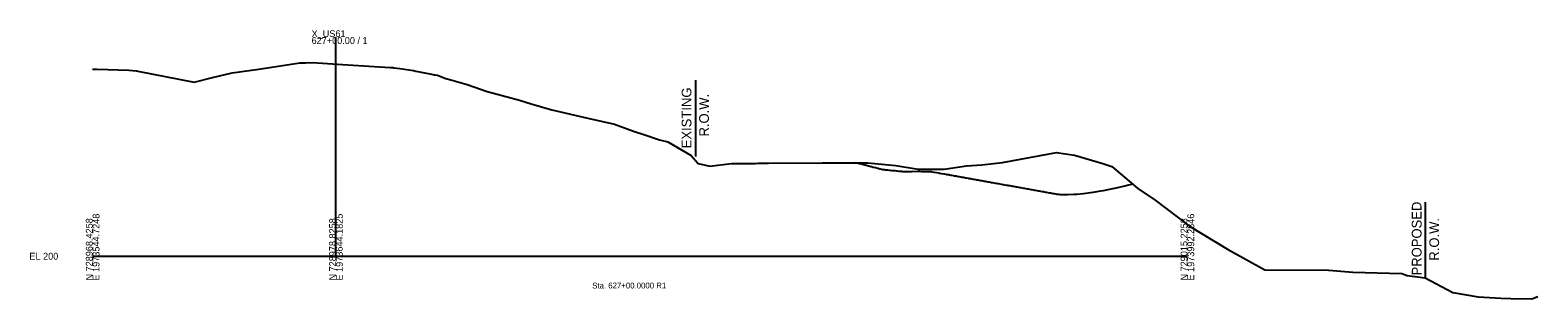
# Model space of a CAD drawing. Extents: x -26 to 630, y -39 to 9098.
# Drawn here: x -26 to 594, y 7482 to 7593 of the extents above; entities that cross this region are included whole.
import ezdxf

# ---------------------------------------------------------------- set-up
doc = ezdxf.new("R2010")
doc.units = 0
for name, color, linetype in [('Default', 7, 'Continuous'), ('Draft_XS_Grid', 7, 'Continuous'), ('Draft_XS_Text', 7, 'Continuous'), ('DTM_X_GROUND', 7, 'Continuous'), ('X_DTM_CONTOURS_MAJOR', 7, 'Continuous'), ('XS_CELL', 7, 'Continuous'), ('XS_P_GROUND', 7, 'Continuous'), ('XS_P_ROW', 7, 'Continuous'), ('XS_X_ROW', 7, 'Continuous')]:
    doc.layers.add(name, color=color, linetype=linetype)

msp = doc.modelspace()

# ---------------------------------------------------------------- linework, layer by layer
at = {"layer": 'DTM_X_GROUND'}
msp.add_lwpolyline([(0, 7576.89), (0.6, 7576.89), (1.9, 7576.85), (14.88, 7576.44), (17.86, 7576.17), (17.96, 7576.16), (18.58, 7576.04), (41.66, 7571.5), (49.31, 7573.36), (57.4, 7575.29), (68.36, 7576.79), (85.15, 7579.38), (87.49, 7579.49), (88.86, 7579.55), (92.36, 7579.36), (102.67, 7578.79), (122.32, 7577.54), (123.58, 7577.45), (123.78, 7577.43), (126.22, 7577.09), (131.88, 7576.23), (132.85, 7576.05), (134.36, 7575.75), (139.24, 7574.76), (140.31, 7574.45), (140.8, 7574.55), (141.71, 7574.4), (144.8, 7573.16), (145.16, 7573.05), (147.21, 7572.46), (154, 7570.58), (162.19, 7567.69), (164.8, 7567), (175.47, 7564.13), (180.27, 7562.58), (188.73, 7560.15), (203.61, 7556.66), (214.46, 7554.19), (222.32, 7551.38), (226.56, 7550.03), (233.04, 7547.84), (236.48, 7546.95), (245.98, 7541.43), (248.95, 7538.09), (253.64, 7537.01), (262.64, 7538.07), (270.68, 7538.05), (272.47, 7538.05), (273.52, 7538.22), (275.9, 7538.18), (277.87, 7538.15), (299.83, 7538.33), (299.94, 7538.33), (299.94, 7538.33), (300.02, 7538.35), (300.35, 7538.4), (318.65, 7538.33), (330.09, 7537.29), (339.33, 7535.72), (350.03, 7535.8), (359.25, 7537.13), (365.54, 7537.58), (373.93, 7538.55), (396.2, 7542.55), (403.53, 7541.51), (415.27, 7538.07), (418.87, 7536.9), (429.65, 7527.82), (436.78, 7523.06), (450.91, 7512.29), (466.52, 7502.84), (481.87, 7494.36), (507.99, 7494.2), (508.1, 7494.2), (508.17, 7494.2), (518.04, 7493.48), (538.13, 7492.96), (540.32, 7492.03), (547.73, 7491.14), (559.09, 7485.1), (569.52, 7483.3), (578.84, 7482.73), (582.95, 7482.65), (591.51, 7482.5), (594.05, 7483.51)], dxfattribs=at)
at = {"layer": 'XS_CELL'}
for p, q in [((100, 7500), (100, 7590)), ((0, 7500), (100, 7500)), ((100, 7500), (450, 7500))]:
    msp.add_line(p, q, dxfattribs=at)
at = {"layer": 'XS_P_GROUND'}
msp.add_lwpolyline([(427.5, 7529.63), (425.19, 7529.04), (424.86, 7528.97), (419.98, 7527.85), (419.15, 7527.68), (415.33, 7526.92), (414.32, 7526.75), (411.07, 7526.2), (408.24, 7525.82), (407.11, 7525.67), (404.54, 7525.4), (403.36, 7525.28), (400.88, 7525.18), (399.35, 7525.15), (398.89, 7525.19), (398.34, 7525.23), (397.88, 7525.27), (397.33, 7525.31), (396.88, 7525.35), (396.36, 7525.4), (396.34, 7525.4), (396.32, 7525.4), (395.86, 7525.49), (395.31, 7525.58), (394.85, 7525.67), (394.3, 7525.76), (393.83, 7525.85), (393.29, 7525.95), (392.82, 7526.03), (392.28, 7526.13), (391.81, 7526.21), (391.27, 7526.31), (390.8, 7526.39), (390.26, 7526.49), (389.79, 7526.57), (389.25, 7526.67), (388.78, 7526.75), (388.24, 7526.85), (387.76, 7526.93), (387.23, 7527.03), (386.75, 7527.12), (386.22, 7527.21), (385.74, 7527.3), (385.21, 7527.39), (384.72, 7527.48), (384.2, 7527.57), (383.71, 7527.66), (383.19, 7527.75), (382.7, 7527.84), (382.18, 7527.93), (381.68, 7528.02), (381.17, 7528.11), (380.67, 7528.2), (380.16, 7528.29), (379.66, 7528.39), (379.15, 7528.48), (378.64, 7528.57), (378.14, 7528.66), (377.63, 7528.75), (377.13, 7528.84), (376.61, 7528.93), (376.12, 7529.02), (375.6, 7529.11), (375.11, 7529.2), (374.58, 7529.29), (374.1, 7529.38), (373.57, 7529.47), (373.09, 7529.56), (372.55, 7529.66), (372.08, 7529.74), (371.54, 7529.84), (371.07, 7529.92), (370.52, 7530.02), (370.06, 7530.1), (369.5, 7530.2), (369.05, 7530.28), (368.49, 7530.38), (368.04, 7530.46), (367.47, 7530.57), (367.03, 7530.64), (366.45, 7530.75), (366.02, 7530.83), (365.44, 7530.93), (365.01, 7531.01), (364.42, 7531.11), (364, 7531.19), (363.4, 7531.29), (362.99, 7531.37), (362.39, 7531.48), (361.98, 7531.55), (361.37, 7531.66), (360.97, 7531.73), (360.35, 7531.84), (359.96, 7531.91), (359.33, 7532.02), (358.95, 7532.09), (358.31, 7532.2), (357.94, 7532.27), (357.3, 7532.39), (356.93, 7532.45), (356.28, 7532.57), (355.92, 7532.63), (355.26, 7532.75), (354.91, 7532.81), (354.23, 7532.93), (353.9, 7532.99), (353.21, 7533.12), (352.89, 7533.18), (352.18, 7533.3), (351.88, 7533.36), (351.14, 7533.49), (350.87, 7533.54), (350.11, 7533.67), (349.86, 7533.72), (349.07, 7533.86), (348.85, 7533.9), (348.04, 7534.04), (347.83, 7534.08), (347.02, 7534.22), (346.82, 7534.26), (345.99, 7534.41), (345.81, 7534.44), (345.06, 7534.58), (344.91, 7534.6), (344.82, 7534.6), (344.8, 7534.6), (343.95, 7534.63), (343.79, 7534.63), (342.94, 7534.65), (342.78, 7534.66), (341.93, 7534.68), (341.77, 7534.68), (340.92, 7534.7), (340.76, 7534.71), (339.91, 7534.73), (339.75, 7534.73), (339.49, 7534.74), (339.44, 7534.74), (339.07, 7534.73), (336.66, 7534.63), (336.11, 7534.63), (333.9, 7534.62), (333.61, 7534.64), (332.88, 7534.7), (332.57, 7534.73), (331.87, 7534.8), (331.56, 7534.83), (330.87, 7534.9), (330.55, 7534.93), (329.87, 7535), (329.55, 7535.03), (328.87, 7535.1), (328.54, 7535.13), (327.87, 7535.2), (327.54, 7535.23), (326.87, 7535.3), (326.55, 7535.33), (325.87, 7535.4), (325.55, 7535.43), (324.87, 7535.5), (324.81, 7535.5), (324.7, 7535.52), (324.43, 7535.58), (323.87, 7535.73), (323.56, 7535.81), (322.87, 7535.98), (322.58, 7536.06), (321.87, 7536.24), (321.6, 7536.31), (320.86, 7536.49), (320.09, 7536.69), (319.86, 7536.75), (319.06, 7536.95), (318.86, 7537), (318.03, 7537.22), (317.86, 7537.26), (316.99, 7537.48), (316.86, 7537.51), (315.95, 7537.75), (315.86, 7537.77), (314.91, 7538.01), (314.86, 7538.02), (313.87, 7538.28), (313.86, 7538.28), (313.6, 7538.35)], dxfattribs=at)
at = {"layer": 'XS_P_ROW'}
msp.add_line((547.73, 7522.16), (547.73, 7491.14), dxfattribs=at)
at = {"layer": 'XS_X_ROW'}
msp.add_line((248, 7540.9), (248, 7572.26), dxfattribs=at)

# ---------------------------------------------------------------- texts
at = {"layer": 'Default'}
for p in [(379.27, 7539.45), (379.27, 7539.45), (419.99, 7535.84), (419.99, 7535.84)]:
    msp.add_text('X', height=0.12, dxfattribs=at).set_placement(p)
at = {"layer": 'Draft_XS_Grid'}
msp.add_text('-', height=0.0001, dxfattribs=at).set_placement((0, 7500))
at = {"layer": 'Draft_XS_Text'}
msp.add_text('Sta. 627+00.0000 R1', height=2.4, dxfattribs=at).set_placement((205.34, 7486.75))
at = {"layer": 'X_DTM_CONTOURS_MAJOR'}
msp.add_text('X', height=0.12, dxfattribs=at).set_placement((238.12, 7558.58))
at = {"layer": 'XS_CELL'}
for s, p in [('X_US61', (90, 7590)), ('627+00.00 / 1', (90, 7587.2)), ('EL 200', (-26, 7498.6))]:
    msp.add_text(s, height=2.8, dxfattribs=at).set_placement(p)
for s, p in [('N 728968.4258', (0, 7490)), ('E 1973544.7248', (2.8, 7490)), ('N 728978.8258', (100, 7490)), ('E 1973644.1825', (102.8, 7490)), ('N 729015.2258', (450, 7490)), ('E 1973992.2846', (452.8, 7490))]:
    msp.add_text(s, height=2.8, rotation=90, dxfattribs=at).set_placement(p)
at = {"layer": 'XS_P_ROW'}
for s, p in [('EXISTING', (246.11, 7544.32)), ('R.O.W.', (253.31, 7549.16)), ('PROPOSED', (546.24, 7492.1)), ('R.O.W.', (553.44, 7498.17))]:
    msp.add_text(s, height=4, rotation=90, dxfattribs=at).set_placement(p)

doc.saveas('drawing.dxf')
